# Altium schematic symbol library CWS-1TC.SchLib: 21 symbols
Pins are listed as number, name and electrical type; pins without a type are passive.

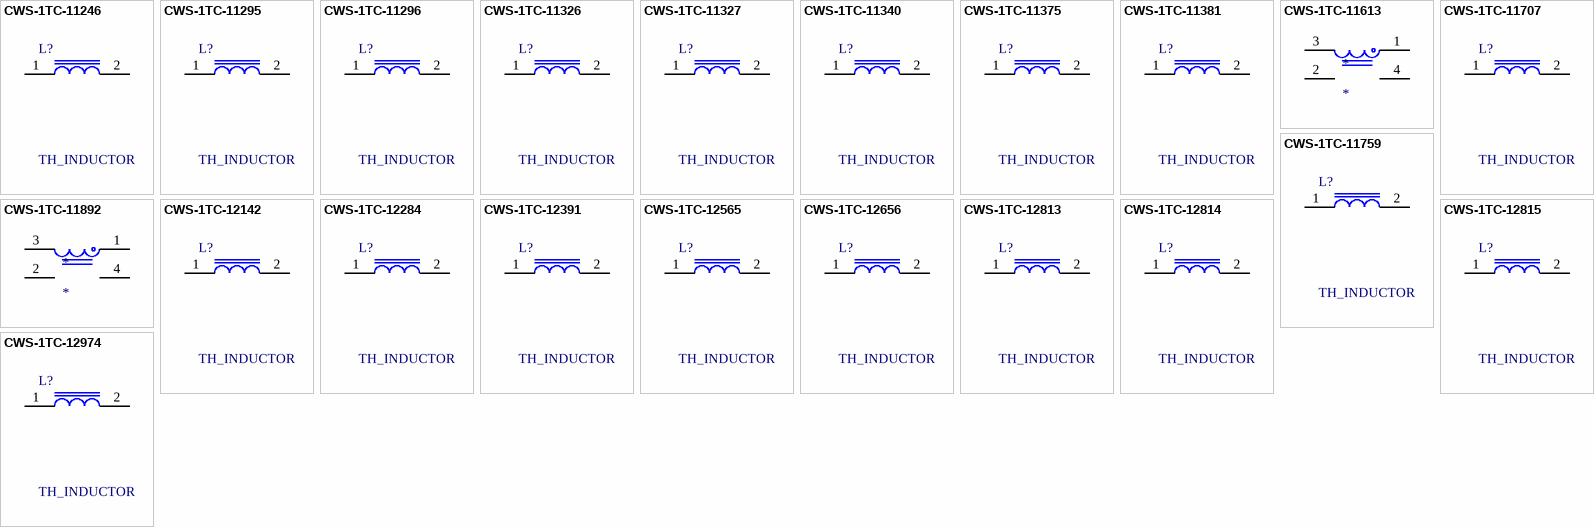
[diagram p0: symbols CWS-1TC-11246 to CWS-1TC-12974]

## CWS-1TC-11246
designator L?, comment TH_INDUCTOR
POWER INDUCTOR 1 A, 6.00 uH , 102 mOhms, OD 14.224 mm, HT 8.636 mm; Manufacturer #1: CWS; Current: 1 A; Inductance: 6 uH
footprint CWS-1TC-11246
pins: 1, 2

## CWS-1TC-11295
designator L?, comment TH_INDUCTOR
POWER INDUCTOR  , 0.50 uH , 0.7 mOhms, OD 23.368 mm, HT 15.494 mm; Manufacturer #1: CWS; Inductance: 0.5 uH
footprint CWS-1TC-11295
pins: 1, 2

## CWS-1TC-11296
designator L?, comment TH_INDUCTOR
POWER INDUCTOR  , 2.40 uH , 1.8 mOhms, OD 22.86 mm, HT 15.494 mm; Manufacturer #1: CWS; Inductance: 2.4 uH
footprint CWS-1TC-11296
pins: 1, 2

## CWS-1TC-11326
designator L?, comment TH_INDUCTOR
POWER INDUCTOR 12 A, 1.25 uH , 3.2 mOhms, OD 20.066 mm, HT 9.906 mm; Manufacturer #1: CWS; Current: 12 A; Inductance: 1.25 uH
footprint CWS-1TC-11326
pins: 1, 2

## CWS-1TC-11327
designator L?, comment TH_INDUCTOR
POWER INDUCTOR 15 A, 0.65 uH , 2.5 mOhms, OD 23.876 mm, HT 12.7 mm; Manufacturer #1: CWS; Current: 15 A; Inductance: 0.65 uH
footprint CWS-1TC-11327
pins: 1, 2

## CWS-1TC-11340
designator L?, comment TH_INDUCTOR
POWER INDUCTOR 7 A, 188.00 uH , 53 mOhms, OD 31.496 mm, HT 16.002 mm; Manufacturer #1: CWS; Current: 7 A; Inductance: 188 uH
footprint CWS-1TC-11340
pins: 1, 2

## CWS-1TC-11375
designator L?, comment TH_INDUCTOR
POWER INDUCTOR 5.5 A, 576.00 uH , 150 mOhms, OD 24.384 mm, HT 33.274 mm; Manufacturer #1: CWS; Current: 5.5 A; Inductance: 576 uH
footprint CWS-1TC-11375
pins: 1, 2

## CWS-1TC-11381
designator L?, comment TH_INDUCTOR
POWER INDUCTOR 6 A, 10.00 uH , 10 mOhms, OD 18.034 mm, HT 10.922 mm; Manufacturer #1: CWS; Current: 6 A; Inductance: 10 uH
footprint CWS-1TC-11381
pins: 1, 2

## CWS-1TC-11613
designator *
POWER INDUCTOR 7.2 A, 700.00 uH , 70 mOhms, OD 52.07 mm, HT 29.21 mm; Manufacturer #1: CWS; Current: 7.2 A; Inductance: 700 uH
footprint CWS-1TC-11613
pins: 1, 2, 3, 4

## CWS-1TC-11707
designator L?, comment TH_INDUCTOR
POWER INDUCTOR 30 A, 190.00 uH , 18 mOhms, OD 65.024 mm, HT 22.098 mm; Manufacturer #1: CWS; Current: 30 A; Inductance: 190 uH
footprint CWS-1TC-11707
pins: 1, 2

## CWS-1TC-11759
designator L?, comment TH_INDUCTOR
POWER INDUCTOR 0.5 A, 361.00 nH , 68 mOhms, OD 7.112 mm, HT 3.556 mm; Manufacturer #1: CWS; Current: 0.5 A; Inductance: 361 nH
footprint CWS-1TC-11759
pins: 1, 2

## CWS-1TC-11892
designator *
POWER INDUCTOR 15 A, 33.00 uH , 12 mOhms, OD 26.67 mm, HT 16.51 mm; Manufacturer #1: CWS; Current: 15 A; Inductance: 33 uH
footprint CWS-1TC-11892
pins: 1, 2, 3, 4

## CWS-1TC-12142
designator L?, comment TH_INDUCTOR
POWER INDUCTOR 15.4 A, 10.00 uH , 6.2 mOhms, OD 25.4 mm, HT 9.398 mm; Manufacturer #1: CWS; OD: 25.4 mm; Current: 15.4 A; Inductance: 10 uH
footprint CWS-1TC-12142
pins: 1, 2

## CWS-1TC-12284
designator L?, comment TH_INDUCTOR
POWER INDUCTOR 10 A, 83.80 uH , 90 mOhms, OD 34.544 mm, HT 18.288 mm; Manufacturer #1: CWS; Current: 10 A; Inductance: 83.8 uH
footprint CWS-1TC-12284
pins: 1, 2

## CWS-1TC-12391
designator L?, comment TH_INDUCTOR
POWER INDUCTOR 5 A, 304.56 uH , 55 mOhms, OD 29.21 mm, HT 18.288 mm; Manufacturer #1: CWS; Current: 5 A
footprint CWS-1TC-12391
pins: 1, 2

## CWS-1TC-12565
designator L?, comment TH_INDUCTOR
POWER INDUCTOR 20 A, 270.00 uH , 36 mOhms, OD 36.068 mm, HT 21.082 mm; Manufacturer #1: CWS; Current: 20 A; Inductance: 270 uH
footprint CWS-1TC-12565
pins: 1, 2

## CWS-1TC-12656
designator L?, comment TH_INDUCTOR
POWER INDUCTOR 0.5 A, 265.00 uH , 350 mOhms, OD 12.7 mm, HT 12.7 mm; Manufacturer #1: CWS; OD: 12.7 mm; Current: 0.5 A; Inductance: 265 uH
footprint CWS-1TC-12656
pins: 1, 2

## CWS-1TC-12813
designator L?, comment TH_INDUCTOR
POWER INDUCTOR  , 2.40 uH , 21 mOhms, OD 15.494 mm, HT 10.414 mm; Manufacturer #1: CWS; Inductance: 2.4 uH
footprint CWS-1TC-12813
pins: 1, 2

## CWS-1TC-12814
designator L?, comment TH_INDUCTOR
POWER INDUCTOR  , 1.02 uH , 0.52 mOhms, OD 15.494 mm, HT 10.414 mm; Manufacturer #1: CWS; Inductance: 1.02 uH
footprint CWS-1TC-12814
pins: 1, 2

## CWS-1TC-12815
designator L?, comment TH_INDUCTOR
POWER INDUCTOR  , 273.00 nH , 7.04 mOhms, OD 16.764 mm, HT 7.874 mm; Manufacturer #1: CWS; Inductance: 273 nH
footprint CWS-1TC-12815
pins: 1, 2

## CWS-1TC-12974
designator L?, comment TH_INDUCTOR
POWER INDUCTOR  , 600.00 uH , 193 mOhms, OD 114.808 mm, HT 49.022 mm; Manufacturer #1: CWS; Inductance: 600 uH
footprint CWS-1TC-12974
pins: 1, 2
